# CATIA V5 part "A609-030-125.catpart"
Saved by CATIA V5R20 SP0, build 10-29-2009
Part number: A609-030-125
Source: Unknown
Property "ARTICLENO": "A609-030-125"
Property "B": "30.000"
Property "BOMINFO": "A609-030-125"
Property "CODE": "A609-030-125"
Property "D": "20.000"
Property "D1": "13.500"
Property "FORM": "A"
Property "L": "125.000"
Property "L1": "25.000"
Property "L2": "75.000"
Property "LINA": "A609-030-125"
Property "NB": "A609-030-125"
Property "NBSYN": "$CODE."
Property "NN": "A609"
Property "NT": "VDI 3357 E-Type Wear Plates, self-lubricating"
Property "S": "30.000"
Property "SUPPLIER": "CF"
Property "T": "13.000"
Property "W": "60.000"
Bounding box of the stored display mesh (mm): x 0 to 125, y 0 to 30, z 0 to 60
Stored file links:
  C:\Users\Utente\Desktop\3D files A609\A609-030-125.catpart
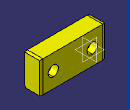
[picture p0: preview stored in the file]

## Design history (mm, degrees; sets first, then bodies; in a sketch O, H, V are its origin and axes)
Body1 "Geometry.1" (main body)
  Solid1 "A609-030-125.catpart": solid without history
